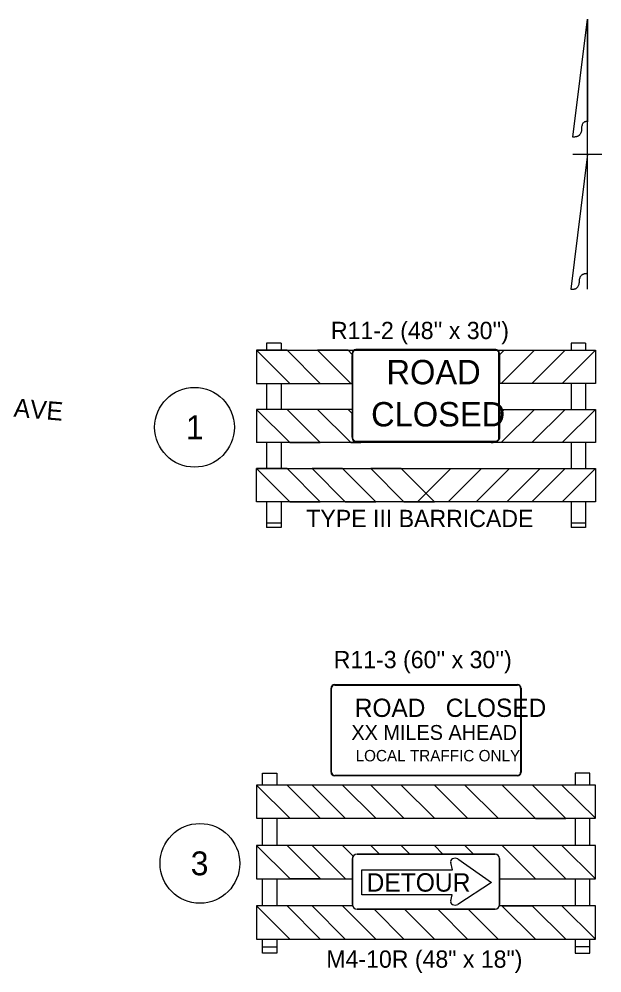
# Model space of a CAD drawing. Extents: x 886234 to 968767, y 455416 to 684046.
# Drawn here: x 921825 to 925786, y 576358 to 582840 of the extents above; entities that cross this region are included whole.
import ezdxf

# ---------------------------------------------------------------- set-up
doc = ezdxf.new("R2010")
doc.units = 0
for name, color, linetype in [('TC DEV BARRICADE', 7, 'Continuous'), ('TC DEV SIGN BLACK 239', 7, 'Continuous'), ('TC DEV SIGN BLACK ZERO', 7, 'Continuous'), ('TC DEV SIGN ORANGE', 7, 'Continuous'), ('TC DEV SIGN WHITE', 7, 'Continuous'), ('TC LABEL TEXT', 7, 'Continuous'), ('TC SHEET LAYOUT SHAPE', 7, 'Continuous')]:
    doc.layers.add(name, color=color, linetype=linetype)

msp = doc.modelspace()

# ---------------------------------------------------------------- linework, layer by layer
at = {"layer": 'TC DEV BARRICADE'}
for p, q in [((923646, 580589.9), (923438.6, 580589.9)), ((923438.6, 580589.9), (923664.5, 580364)), ((923438.6, 580589.9), (923438.6, 580364)), ((923438.6, 580589.9), (925742.6, 580589.9)), ((923604.9, 580638.8), (923507.1, 580638.8)), ((923507.1, 580638.8), (923507.1, 580589.9)), ((923604.9, 580638.8), (923604.9, 580589.9)), ((923871.9, 580364), (923646, 580589.9)), ((924060.6, 580589.9), (923853.3, 580589.9)), ((923853.3, 580589.9), (924079.2, 580364)), ((924089.6, 580560.9), (924060.6, 580589.9)), ((925091.6, 580560.9), (925120.7, 580589.9)), ((925328, 580589.9), (925102.1, 580364)), ((925120.7, 580589.9), (925328, 580589.9)), ((925309.4, 580364), (925535.3, 580589.9)), ((925742.6, 580589.9), (925516.7, 580364)), ((925535.3, 580589.9), (925742.6, 580589.9)), ((925674.2, 580638.8), (925576.4, 580638.8)), ((925576.4, 580638.8), (925576.4, 580589.9)), ((925674.2, 580638.8), (925674.2, 580589.9)), ((925742.6, 580589.9), (925742.6, 580364)), ((924088.4, 580364), (924088.4, 580553.3)), ((925092.9, 580364), (925092.9, 580553.3)), ((923438.6, 580364), (924088.4, 580364)), ((923507.1, 580364), (923507.1, 580188)), ((923604.9, 580364), (923604.9, 580188)), ((923664.5, 580364), (923871.9, 580364)), ((924079.2, 580364), (924088.4, 580364)), ((925102.1, 580364), (925092.9, 580364)), ((925742.6, 580364), (925092.9, 580364)), ((925516.7, 580364), (925309.4, 580364)), ((925576.4, 580364), (925576.4, 580188)), ((925674.2, 580364), (925674.2, 580188)), ((923438.6, 580188), (923438.6, 579962.1)), ((923646, 580188), (923438.6, 580188)), ((923438.6, 580188), (923664.5, 579962.1)), ((924088.4, 580188), (923438.6, 580188)), ((923871.9, 579962.1), (923646, 580188)), ((923853.3, 580188), (924079.2, 579962.1)), ((924060.6, 580188), (923853.3, 580188)), ((924088.4, 580160.2), (924060.6, 580188)), ((924088.4, 579998.7), (924088.4, 580160.2)), ((925092.9, 580160.2), (925120.7, 580188)), ((925092.9, 580188), (925742.6, 580188)), ((925092.9, 579998.7), (925092.9, 580160.2)), ((925328, 580188), (925102.1, 579962.1)), ((925120.7, 580188), (925328, 580188)), ((925309.4, 579962.1), (925535.3, 580188)), ((925742.6, 580188), (925516.7, 579962.1)), ((925535.3, 580188), (925742.6, 580188)), ((925742.6, 580188), (925742.6, 579962.1)), ((925742.6, 579962.1), (923438.6, 579962.1)), ((923507.1, 579962.1), (923507.1, 579786.1)), ((923604.9, 579962.1), (923604.9, 579786.1)), ((923664.5, 579962.1), (923871.9, 579962.1)), ((924079.2, 579962.1), (924146.6, 579962.1)), ((925102.1, 579962.1), (925034.7, 579962.1)), ((925516.7, 579962.1), (925309.4, 579962.1)), ((925576.4, 579962.1), (925576.4, 579786.1)), ((925674.2, 579962.1), (925674.2, 579786.1)), ((923646, 579786.1), (923438.6, 579786.1)), ((923438.6, 579786.1), (923664.3, 579560.4)), ((923871.8, 579560.2), (923646, 579786.1)), ((924023.3, 579785.9), (923816, 579785.9)), ((923816, 579785.9), (924041.7, 579560.2)), ((924249.1, 579560.1), (924023.3, 579785.9)), ((924421.9, 579786.1), (924214.6, 579786.1)), ((924214.6, 579786.1), (924440.3, 579560.4)), ((924647.8, 579560.2), (924421.9, 579786.1)), ((924533.5, 579560.2), (924759.4, 579786.1)), ((924966.7, 579786.1), (924741, 579560.4)), ((924759.4, 579786.1), (924966.7, 579786.1)), ((924932.1, 579560.1), (925158, 579785.9)), ((925365.3, 579785.9), (925139.6, 579560.2)), ((925158, 579785.9), (925365.3, 579785.9)), ((925309.5, 579560.2), (925535.3, 579786.1)), ((925742.6, 579786.1), (925516.9, 579560.4)), ((925535.3, 579786.1), (925742.6, 579786.1)), ((923507.1, 579560.2), (923507.1, 579384.1)), ((923604.9, 579560.2), (923604.9, 579384.1)), ((923664.3, 579560.4), (923871.8, 579560.2)), ((924041.7, 579560.2), (924249.1, 579560.1)), ((924440.3, 579560.4), (924647.8, 579560.2)), ((924741, 579560.4), (924533.5, 579560.2)), ((925139.6, 579560.2), (924932.1, 579560.1)), ((925516.9, 579560.4), (925309.5, 579560.2)), ((925576.4, 579560.2), (925576.4, 579384.1)), ((925674.2, 579560.2), (925674.2, 579384.1)), ((923604.9, 579413.5), (923507.1, 579413.5)), ((923604.9, 579384.1), (923507.1, 579384.1)), ((925674.2, 579413.5), (925576.4, 579413.5)), ((925674.2, 579384.1), (925576.4, 579384.1)), ((923646, 577634.9), (923438.6, 577634.9)), ((923438.6, 577634.9), (923664.3, 577409.2)), ((923871.8, 577409), (923646, 577634.9)), ((924023.3, 577634.7), (923816, 577634.7)), ((923816, 577634.7), (924041.7, 577409)), ((924249.1, 577408.9), (924023.3, 577634.7)), ((924421.9, 577634.9), (924214.6, 577634.9)), ((924214.6, 577634.9), (924440.3, 577409.2)), ((924647.8, 577409.1), (924421.9, 577634.9)), ((924854.7, 577634.6), (924647.4, 577634.6)), ((924647.4, 577634.6), (924873.1, 577408.9)), ((925080.6, 577408.7), (924854.7, 577634.6)), ((925315.3, 577633.7), (925107.9, 577633.7)), ((925107.9, 577633.7), (925333.7, 577408)), ((925541.1, 577407.8), (925315.3, 577633.7)), ((925742.6, 577634.9), (925513.8, 577634.9)), ((925513.8, 577634.9), (925742.6, 577409)), ((925742.6, 577409), (925742.6, 577634.9)), ((923664.3, 577409.2), (923871.8, 577409)), ((924041.7, 577409), (924249.1, 577408.9)), ((924440.3, 577409.2), (924647.8, 577409.1)), ((924873.1, 577408.9), (925080.6, 577408.7)), ((925333.7, 577408), (925541.1, 577407.8)), ((923646, 577224.2), (923438.6, 577224.2)), ((923438.6, 577224.2), (923664.3, 576998.5)), ((923871.8, 576998.4), (923646, 577224.2)), ((924023.3, 577224.1), (923816, 577224.1)), ((923816, 577224.1), (924041.7, 576998.4)), ((924023.3, 577224.1), (923816, 577224.1)), ((923816, 577224.1), (924041.7, 576998.4)), ((924095.6, 577151.7), (924023.3, 577224.1)), ((924095.6, 577151.7), (924023.3, 577224.1)), ((924421.9, 577224.3), (924214.6, 577224.3)), ((924214.6, 577224.3), (924273.2, 577165.6)), ((924214.6, 577224.2), (924273.2, 577165.6)), ((924480.5, 577165.6), (924421.9, 577224.3)), ((924480.5, 577165.6), (924421.9, 577224.2)), ((924854.7, 577223.9), (924647.4, 577223.9)), ((924647.4, 577223.9), (924705.7, 577165.6)), ((924854.7, 577223.9), (924647.4, 577223.9)), ((924647.4, 577223.9), (924705.7, 577165.6)), ((924913, 577165.6), (924854.7, 577223.9)), ((924913, 577165.6), (924854.7, 577223.9)), ((925315.3, 577223), (925107.9, 577223)), ((925107.9, 577223), (925333.7, 576997.3)), ((925541.1, 576997.2), (925315.3, 577223)), ((925742.6, 577224.2), (925513.8, 577224.2)), ((925513.8, 577224.2), (925742.6, 576998.3)), ((925742.6, 576998.3), (925742.6, 577224.2)), ((924273.2, 577165.6), (924480.5, 577165.6)), ((924705.7, 577165.6), (924913, 577165.6)), ((924090.3, 576998.3), (924090.3, 577134.4)), ((923664.3, 576998.5), (923871.8, 576998.4)), ((924041.7, 576998.4), (924090.3, 576998.3)), ((924041.7, 576998.4), (924090.3, 576998.3)), ((925333.7, 576997.3), (925541.1, 576997.2)), ((923646, 576813.5), (923438.6, 576813.5)), ((923438.6, 576813.5), (923664.3, 576587.8)), ((923871.8, 576587.7), (923646, 576813.5)), ((924023.3, 576813.4), (923816, 576813.4)), ((923816, 576813.4), (924041.7, 576587.7)), ((924249.1, 576587.5), (924023.3, 576813.4)), ((924237.8, 576790.4), (924440.3, 576587.9)), ((924237.8, 576790.4), (924440.3, 576587.9)), ((924445.1, 576790.4), (924237.8, 576790.4)), ((924647.8, 576587.7), (924445.1, 576790.4)), ((924647.8, 576587.7), (924445.1, 576790.4)), ((924670.2, 576790.4), (924873.1, 576587.5)), ((924877.5, 576790.4), (924670.2, 576790.4)), ((924670.2, 576790.4), (924873, 576587.6)), ((925080.6, 576587.4), (924877.5, 576790.4)), ((925080.3, 576587.6), (924877.5, 576790.4)), ((925315.3, 576812.3), (925107.9, 576812.3)), ((925107.9, 576812.3), (925333.7, 576586.6)), ((925541.1, 576586.5), (925315.3, 576812.3)), ((925742.6, 576813.5), (925513.8, 576813.5)), ((925513.8, 576813.5), (925742.6, 576587.6)), ((925742.6, 576587.6), (925742.6, 576813.5)), ((923664.3, 576587.8), (923871.8, 576587.7)), ((924041.7, 576587.7), (924249.1, 576587.5)), ((924440.3, 576587.9), (924647.8, 576587.7)), ((924440.3, 576587.9), (924647.8, 576587.7)), ((924873.1, 576587.5), (925080.6, 576587.4)), ((925333.7, 576586.6), (925541.1, 576586.5)), ((923478.1, 576535.8), (923576.6, 576535.8)), ((925703.1, 576535.8), (925604.6, 576535.8))]:
    msp.add_line(p, q, dxfattribs=at)
for points in [[(925155.1, 579786.1), (925742.6, 579786.1), (925742.6, 579560.2), (923438.6, 579560.2), (923438.6, 579786.1), (923979.7, 579786.1)], [(923979.7, 579786.1), (925155.1, 579786.1)], [(923478.1, 577636.6), (923478.1, 577716.4), (923576.6, 577716.4), (923576.6, 577636.8)], [(925703.1, 577636.6), (925703.1, 577716.4), (925604.6, 577716.4), (925604.6, 577636.8)], [(924026.1, 577634.9), (923438.6, 577634.9), (923438.6, 577409), (925742.6, 577409), (925742.6, 577634.9), (925201.5, 577634.9)], [(925201.5, 577634.9), (924026.1, 577634.9)], [(923478.1, 577226.3), (923478.1, 577409.7)], [(923576.6, 577410.7), (923576.6, 577228.9)], [(925604.6, 577410.7), (925604.6, 577228.9)], [(925703.1, 577226.3), (925703.1, 577409.7)], [(924026.1, 577224.2), (923438.6, 577224.2), (923438.6, 576998.3), (924090.3, 576998.3)], [(925201.5, 577224.2), (924026.1, 577224.2)], [(924421.9, 577224.2), (924421.9, 577224.2), (924214.6, 577224.2)], [(925090.9, 576998.3), (925742.6, 576998.3), (925742.6, 577224.2), (925201.5, 577224.2)], [(923478.1, 576813.5), (923478.1, 576998.2)], [(923576.6, 576997.2), (923576.6, 576815.4)], [(925604.6, 576997.2), (925604.6, 576815.4)], [(925703.1, 576813.5), (925703.1, 576998.2)], [(924026.1, 576813.5), (923438.6, 576813.5), (923438.6, 576587.6), (925742.6, 576587.6), (925742.6, 576813.5), (925201.5, 576813.5)], [(924090.3, 576813.5), (924026.1, 576813.5)], [(925201.5, 576813.5), (925090.9, 576813.5)], [(923576.6, 576586.4), (923576.6, 576491.5), (923478.1, 576491.5), (923478.1, 576587.3)], [(924873, 576587.6), (924873.1, 576587.6), (925080.3, 576587.6)], [(925604.6, 576586.4), (925604.6, 576491.5), (925703.1, 576491.5), (925703.1, 576587.3)]]:
    msp.add_lwpolyline(points, dxfattribs=at)
msp.add_arc((924121.6, 577134.4), 31.3, 146.23597, 180, dxfattribs=at)
for centre, major_axis, start_param, end_param in [((924147, 580553.3), (-58.6, 0), 6.074789, 6.283185), ((925034.3, 580553.3), (58.6, 0), 6.283185, 6.491582), ((924147, 579998.7), (58.6, 0), 3.141593, 4.712389), ((925034.3, 579998.7), (-58.6, 0), 1.570796, 3.141593)]:
    msp.add_ellipse(centre, major_axis=major_axis, ratio=0.625, start_param=start_param, end_param=end_param, dxfattribs=at)
at = {"layer": 'TC DEV SIGN BLACK 239'}
for p, q in [((924113.7, 579968.3), (925064.2, 579968.3)), ((925211.6, 577696.6), (923969.7, 577696.6))]:
    msp.add_line(p, q, dxfattribs=at)
for points in [[(925064.2, 580593.7), (924113.7, 580593.7)], [(924088.7, 580568.6), (924088.7, 579993.3)], [(925089.2, 579993.3), (925089.2, 580568.6)], [(923969.7, 578317.5), (925211.6, 578317.5)], [(923944.9, 577721.4), (923944.9, 578292.7)], [(925236.4, 578292.7), (925236.4, 577721.4)]]:
    msp.add_lwpolyline(points, dxfattribs=at)
for centre, radius, start, end in [((924113.7, 580568.6), 25, 90, 180), ((925064.2, 580568.6), 25, 360, 90), ((924113.7, 579993.3), 25, 180, 269.99914), ((925064.2, 579993.3), 25, 269.99914, 0), ((923969.7, 578292.7), 24.8, 90, 180), ((925211.6, 578292.7), 24.8, 0, 90), ((923969.7, 577721.4), 24.8, 180, 270.00086), ((925211.6, 577721.4), 24.8, 270.00086, 360)]:
    msp.add_arc(centre, radius, start, end, dxfattribs=at)
at = {"layer": 'TC DEV SIGN BLACK ZERO'}
for p, q in [((925059.6, 577165.6), (924121.6, 577165.6)), ((924090.3, 577134.4), (924090.3, 576821.7)), ((924770.4, 577058), (924759.4, 577107.5)), ((924807.5, 577133.3), (925034.6, 576972.7)), ((925090.9, 576821.7), (925090.9, 577134.4)), ((924153.9, 576889.5), (924153.9, 577058)), ((924153.9, 577058), (924770.4, 577058)), ((925034.6, 576972.7), (924807.5, 576822.8)), ((924769.3, 576889.5), (924153.9, 576889.5)), ((924759.4, 576848.5), (924769.3, 576889.5)), ((924121.6, 576790.4), (925059.6, 576790.4))]:
    msp.add_line(p, q, dxfattribs=at)
for points in [[(924121.6, 577165.6), (925059.6, 577165.6)], [(924090.3, 576821.7), (924090.3, 577134.4)], [(925090.9, 577134.4), (925090.9, 576821.7)], [(925059.6, 576790.4), (924121.6, 576790.4)]]:
    msp.add_lwpolyline(points, dxfattribs=at)
for centre, start, end in [((924121.6, 577134.4), 90, 180), ((924121.6, 577134.4), 90, 180), ((925059.6, 577134.4), 360, 90), ((925059.6, 577134.4), 360, 90), ((924121.6, 576821.7), 180, 270), ((924121.6, 576821.7), 180, 270), ((925059.6, 576821.7), 270, 0), ((925059.6, 576821.7), 270, 360)]:
    msp.add_arc(centre, 31.3, start, end, dxfattribs=at)
for centre, start_param, end_param in [((924789.6, 577114.5), 0.96961, 3.452569), ((924789.6, 576841.6), 2.830617, 5.313577)]:
    msp.add_ellipse(centre, major_axis=(31.7, 0), ratio=0.720018, start_param=start_param, end_param=end_param, dxfattribs=at)
at = {"layer": 'TC DEV SIGN ORANGE'}
for p, q in [((924770.4, 577058), (924759.4, 577107.5)), ((924807.5, 577133.3), (925034.6, 576972.7)), ((924153.9, 576889.5), (924153.9, 577058)), ((924153.9, 577058), (924770.4, 577058)), ((925034.6, 576972.7), (924807.5, 576822.8)), ((924769.3, 576889.5), (924153.9, 576889.5)), ((924759.4, 576848.5), (924769.3, 576889.5))]:
    msp.add_line(p, q, dxfattribs=at)
for centre, start_param, end_param in [((924789.6, 577114.5), 0.96961, 3.452569), ((924789.6, 576841.6), 2.830617, 5.313577)]:
    msp.add_ellipse(centre, major_axis=(31.7, 0), ratio=0.720018, start_param=start_param, end_param=end_param, dxfattribs=at)
at = {"layer": 'TC DEV SIGN WHITE'}
for p, q in [((924113.7, 579971.4), (925064.2, 579971.4)), ((925211.6, 577699.7), (923969.7, 577699.7))]:
    msp.add_line(p, q, dxfattribs=at)
for points in [[(925064.2, 580590.5), (924113.7, 580590.5)], [(924091.8, 580568.6), (924091.8, 579993.3)], [(925086.1, 579993.3), (925086.1, 580568.6)], [(923969.7, 578314.4), (925211.6, 578314.4)], [(923948, 577721.4), (923948, 578292.7)], [(925233.3, 578292.7), (925233.3, 577721.4)]]:
    msp.add_lwpolyline(points, dxfattribs=at)
for centre, radius, start, end in [((924113.7, 580568.6), 21.9, 90, 180), ((925064.2, 580568.6), 21.9, 360, 90), ((924113.7, 579993.3), 21.9, 180, 269.99914), ((925064.2, 579993.3), 21.9, 269.99914, 0), ((923969.7, 578292.7), 21.7, 90, 180), ((925211.6, 578292.7), 21.7, 0, 90), ((923969.7, 577721.4), 21.7, 180, 270.00086), ((925211.6, 577721.4), 21.7, 270.00086, 360)]:
    msp.add_arc(centre, radius, start, end, dxfattribs=at)
at = {"layer": 'TC LABEL TEXT'}
for centre in [(923017.1, 580066), (923053.9, 577102.3)]:
    msp.add_circle(centre, 270.9, dxfattribs=at)
at = {"layer": 'TC SHEET LAYOUT SHAPE'}
for p, q in [((925589.2, 582038.9), (925687.6, 582840.4)), ((925589.2, 582038.9), (925687.6, 582840.4)), ((925687.6, 582840.4), (925687.5, 582143)), ((925687.6, 582840.4), (925687.5, 582143)), ((925687.6, 581003.9), (925687.6, 582840.4)), ((925687.6, 581922.1), (925574.9, 581003.9)), ((925589.2, 581922.1), (925786.1, 581922.1)), ((925687.3, 581112.4), (925687.6, 581922.1))]:
    msp.add_line(p, q, dxfattribs=at)
for points in [[(925687.7, 582142.9), (925648.1, 582148.4), (925646.3, 582036), (925589.2, 582038.9)], [(925687.7, 582142.9), (925648.1, 582148.4), (925646.3, 582036), (925589.2, 582038.9)], [(925574.9, 581003.9), (925631.9, 581000.9), (925633.8, 581113.3), (925687.3, 581112.4)]]:
    msp.add_open_spline(points, degree=2, dxfattribs=at)

# ---------------------------------------------------------------- texts
at = {"layer": 'TC DEV BARRICADE'}
for s, p in [("R11-2 (48'' x 30'')", (923944.2, 580665.4)), ('TYPE III BARRICADE', (923776.8, 579387.7)), ("R11-3 (60'' x 30'')", (923963.3, 578428.8)), ('M4-10R (48" x 18")', (923913.1, 576393.1))]:
    msp.add_text(s, height=117.351, dxfattribs=at).set_placement(p)
at = {"layer": 'TC DEV SIGN BLACK 239'}
for s, p in [('ROAD', (924321.6, 580358.3)), ('CLOSED', (924217.3, 580071.9))]:
    msp.add_text(s, height=165.72, dxfattribs=at).set_placement(p)
for s, height, p in [('ROAD   CLOSED', 124.186, (924106.4, 578097.6)), ('XX MILES AHEAD', 100.901, (924083.3, 577941.6)), ('LOCAL TRAFFIC ONLY', 77.616, (924111.8, 577795.5))]:
    msp.add_text(s, height=height, rotation=360, dxfattribs=at).set_placement(p)
at = {"layer": 'TC DEV SIGN BLACK ZERO'}
msp.add_text('DETOUR', height=125.07, dxfattribs=at).set_placement((924186.4, 576910.2))
at = {"layer": 'TC LABEL TEXT'}
msp.add_text('HAYWOOD AVE', height=125, rotation=355.20331, dxfattribs=at).set_placement((920859.2, 580216))
for s, p in [('1', (922958.1, 579985)), ('3', (922991.5, 577021.3))]:
    msp.add_text(s, height=162, dxfattribs=at).set_placement(p)

doc.saveas('drawing.dxf')
